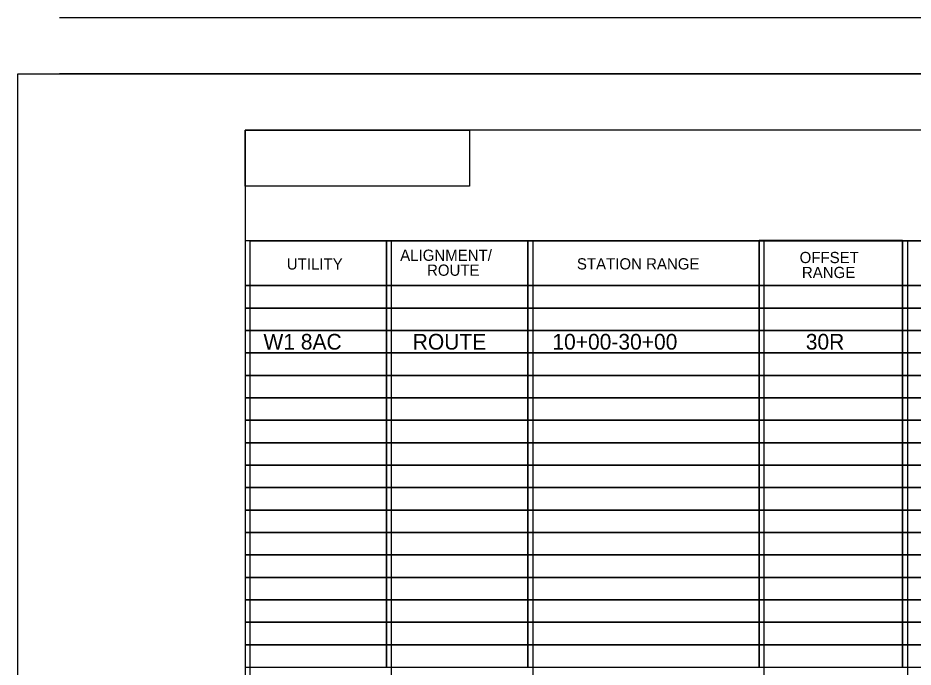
# Model space of a CAD drawing. Extents: x 11473 to 13269, y 16929 to 18079.
# Drawn here: x 11472.6 to 11871.5, y 17790 to 18079.4 of the extents above; entities that cross this region are included whole.
import ezdxf

# ---------------------------------------------------------------- set-up
doc = ezdxf.new("R2010")
doc.units = 0
for name, color, linetype in [('RD_SHT_Bndy', 7, 'Continuous'), ('RD_SHT_Iplotshp', 7, 'Continuous'), ('RD_SHT_Misc2', 7, 'Continuous'), ('RD_SHT_Snap', 7, 'Continuous'), ('RD_SHT_TX', 7, 'Continuous')]:
    doc.layers.add(name, color=color, linetype=linetype)

msp = doc.modelspace()

# ---------------------------------------------------------------- linework, layer by layer
at = {"layer": 'RD_SHT_Bndy'}
for p, q in [((13251.23, 18079.35), (11491.23, 18079.35)), ((13251.23, 18054.35), (11491.23, 18054.35)), ((13248.83, 18029.35), (11573.83, 18029.35)), ((11573.83, 18029.35), (11573.83, 16979.35))]:
    msp.add_line(p, q, dxfattribs=at)
for points in [[(11573.88, 18004.35), (11573.88, 18029.35), (11673.88, 18029.35), (11673.88, 18004.35)], [(11636.83, 17980), (11573.83, 17980), (11573.83, 17960), (11636.83, 17960)], [(11636.83, 17960), (11699.83, 17960), (11699.83, 17980), (11636.83, 17980)], [(11699.83, 17960), (11802.84, 17960), (11802.84, 17980), (11699.83, 17980)], [(11802.84, 17960), (11866.84, 17960), (11866.84, 17980.06), (11802.84, 17980.06)], [(11866.84, 17960), (11973.81, 17960), (11973.81, 17980.01), (11866.84, 17980.01)], [(11573.83, 17950), (11636.83, 17950), (11636.83, 17960), (11573.83, 17960)], [(11636.83, 17950), (11699.83, 17950), (11699.83, 17960), (11636.83, 17960)], [(11699.83, 17950), (11802.84, 17950), (11802.84, 17960), (11699.83, 17960)], [(11802.84, 17950), (11866.84, 17950), (11866.84, 17960), (11802.84, 17960)], [(11866.84, 17950), (11973.81, 17950), (11973.81, 17960), (11866.84, 17960)], [(11573.83, 17939.99), (11636.83, 17939.99), (11636.83, 17950), (11573.83, 17950)], [(11636.83, 17939.99), (11699.83, 17939.99), (11699.83, 17950), (11636.83, 17950)], [(11699.83, 17939.99), (11802.84, 17939.99), (11802.84, 17950), (11699.83, 17950)], [(11802.84, 17939.99), (11866.84, 17939.99), (11866.84, 17950), (11802.84, 17950)], [(11866.84, 17939.99), (11973.81, 17939.99), (11973.81, 17950), (11866.84, 17950)], [(11573.83, 17929.99), (11636.83, 17929.99), (11636.83, 17939.99), (11573.83, 17939.99)], [(11636.83, 17929.99), (11699.83, 17929.99), (11699.83, 17939.99), (11636.83, 17939.99)], [(11699.83, 17929.99), (11802.84, 17929.99), (11802.84, 17939.99), (11699.83, 17939.99)], [(11802.84, 17929.99), (11866.84, 17929.99), (11866.84, 17939.99), (11802.84, 17939.99)], [(11866.84, 17929.99), (11973.81, 17929.99), (11973.81, 17939.99), (11866.84, 17939.99)], [(11573.83, 17919.99), (11636.83, 17919.99), (11636.83, 17929.99), (11573.83, 17929.99)], [(11636.83, 17919.99), (11699.83, 17919.99), (11699.83, 17929.99), (11636.83, 17929.99)], [(11699.83, 17919.99), (11802.84, 17919.99), (11802.84, 17929.99), (11699.83, 17929.99)], [(11802.84, 17919.99), (11866.84, 17919.99), (11866.84, 17929.99), (11802.84, 17929.99)], [(11866.84, 17919.99), (11973.81, 17919.99), (11973.81, 17929.99), (11866.84, 17929.99)], [(11573.83, 17909.98), (11636.83, 17909.98), (11636.83, 17919.99), (11573.83, 17919.99)], [(11636.83, 17909.98), (11699.83, 17909.98), (11699.83, 17919.99), (11636.83, 17919.99)], [(11699.83, 17909.98), (11802.84, 17909.98), (11802.84, 17919.99), (11699.83, 17919.99)], [(11802.84, 17909.98), (11866.84, 17909.98), (11866.84, 17919.99), (11802.84, 17919.99)], [(11866.84, 17909.98), (11973.81, 17909.98), (11973.81, 17919.99), (11866.84, 17919.99)], [(11573.83, 17899.98), (11636.83, 17899.98), (11636.83, 17909.98), (11573.83, 17909.98)], [(11636.83, 17899.98), (11699.83, 17899.98), (11699.83, 17909.98), (11636.83, 17909.98)], [(11699.83, 17899.98), (11802.84, 17899.98), (11802.84, 17909.98), (11699.83, 17909.98)], [(11802.84, 17899.98), (11866.84, 17899.98), (11866.84, 17909.98), (11802.84, 17909.98)], [(11866.84, 17899.98), (11973.81, 17899.98), (11973.81, 17909.98), (11866.84, 17909.98)], [(11573.83, 17889.97), (11636.83, 17889.97), (11636.83, 17899.98), (11573.83, 17899.98)], [(11636.83, 17889.97), (11699.83, 17889.97), (11699.83, 17899.98), (11636.83, 17899.98)], [(11699.83, 17889.97), (11802.84, 17889.97), (11802.84, 17899.98), (11699.83, 17899.98)], [(11802.84, 17889.97), (11866.84, 17889.97), (11866.84, 17899.98), (11802.84, 17899.98)], [(11866.84, 17889.97), (11973.81, 17889.97), (11973.81, 17899.98), (11866.84, 17899.98)], [(11573.83, 17879.97), (11636.83, 17879.97), (11636.83, 17889.97), (11573.83, 17889.97)], [(11636.83, 17879.97), (11699.83, 17879.97), (11699.83, 17889.97), (11636.83, 17889.97)], [(11699.83, 17879.97), (11802.84, 17879.97), (11802.84, 17889.97), (11699.83, 17889.97)], [(11802.84, 17879.97), (11866.84, 17879.97), (11866.84, 17889.97), (11802.84, 17889.97)], [(11866.84, 17879.97), (11973.81, 17879.97), (11973.81, 17889.97), (11866.84, 17889.97)], [(11573.83, 17869.96), (11636.83, 17869.96), (11636.83, 17879.97), (11573.83, 17879.97)], [(11636.83, 17869.96), (11699.83, 17869.96), (11699.83, 17879.97), (11636.83, 17879.97)], [(11699.83, 17869.96), (11802.84, 17869.96), (11802.84, 17879.97), (11699.83, 17879.97)], [(11802.84, 17869.96), (11866.84, 17869.96), (11866.84, 17879.97), (11802.84, 17879.97)], [(11866.84, 17869.96), (11973.81, 17869.96), (11973.81, 17879.97), (11866.84, 17879.97)], [(11573.83, 17859.96), (11636.83, 17859.96), (11636.83, 17869.96), (11573.83, 17869.96)], [(11636.83, 17859.96), (11699.83, 17859.96), (11699.83, 17869.96), (11636.83, 17869.96)], [(11699.83, 17859.96), (11802.84, 17859.96), (11802.84, 17869.96), (11699.83, 17869.96)], [(11802.84, 17859.96), (11866.84, 17859.96), (11866.84, 17869.96), (11802.84, 17869.96)], [(11866.84, 17859.96), (11973.81, 17859.96), (11973.81, 17869.96), (11866.84, 17869.96)], [(11573.83, 17849.96), (11636.83, 17849.96), (11636.83, 17859.96), (11573.83, 17859.96)], [(11636.83, 17849.96), (11699.83, 17849.96), (11699.83, 17859.96), (11636.83, 17859.96)], [(11699.83, 17849.96), (11802.84, 17849.96), (11802.84, 17859.96), (11699.83, 17859.96)], [(11802.84, 17849.96), (11866.84, 17849.96), (11866.84, 17859.96), (11802.84, 17859.96)], [(11866.84, 17849.96), (11973.81, 17849.96), (11973.81, 17859.96), (11866.84, 17859.96)], [(11573.83, 17839.95), (11636.83, 17839.95), (11636.83, 17849.96), (11573.83, 17849.96)], [(11636.83, 17839.95), (11699.83, 17839.95), (11699.83, 17849.96), (11636.83, 17849.96)], [(11699.83, 17839.95), (11802.84, 17839.95), (11802.84, 17849.96), (11699.83, 17849.96)], [(11802.84, 17839.95), (11866.84, 17839.95), (11866.84, 17849.96), (11802.84, 17849.96)], [(11866.84, 17839.95), (11973.81, 17839.95), (11973.81, 17849.96), (11866.84, 17849.96)], [(11573.83, 17829.95), (11636.83, 17829.95), (11636.83, 17839.95), (11573.83, 17839.95)], [(11636.83, 17829.95), (11699.83, 17829.95), (11699.83, 17839.95), (11636.83, 17839.95)], [(11699.83, 17829.95), (11802.84, 17829.95), (11802.84, 17839.95), (11699.83, 17839.95)], [(11802.84, 17829.95), (11866.84, 17829.95), (11866.84, 17839.95), (11802.84, 17839.95)], [(11866.84, 17829.95), (11973.81, 17829.95), (11973.81, 17839.95), (11866.84, 17839.95)], [(11573.83, 17819.94), (11636.83, 17819.94), (11636.83, 17829.95), (11573.83, 17829.95)], [(11636.83, 17819.94), (11699.83, 17819.94), (11699.83, 17829.95), (11636.83, 17829.95)], [(11699.83, 17819.94), (11802.84, 17819.94), (11802.84, 17829.95), (11699.83, 17829.95)], [(11802.84, 17819.94), (11866.84, 17819.94), (11866.84, 17829.95), (11802.84, 17829.95)], [(11866.84, 17819.94), (11973.81, 17819.94), (11973.81, 17829.95), (11866.84, 17829.95)], [(11573.83, 17809.94), (11636.83, 17809.94), (11636.83, 17819.94), (11573.83, 17819.94)], [(11636.83, 17809.94), (11699.83, 17809.94), (11699.83, 17819.94), (11636.83, 17819.94)], [(11699.83, 17809.94), (11802.84, 17809.94), (11802.84, 17819.94), (11699.83, 17819.94)], [(11802.84, 17809.94), (11866.84, 17809.94), (11866.84, 17819.94), (11802.84, 17819.94)], [(11866.84, 17809.94), (11973.81, 17809.94), (11973.81, 17819.94), (11866.84, 17819.94)], [(11573.83, 17799.93), (11636.83, 17799.93), (11636.83, 17809.94), (11573.83, 17809.94)], [(11636.83, 17799.93), (11699.83, 17799.93), (11699.83, 17809.94), (11636.83, 17809.94)], [(11699.83, 17799.93), (11802.84, 17799.93), (11802.84, 17809.94), (11699.83, 17809.94)], [(11802.84, 17799.93), (11866.84, 17799.93), (11866.84, 17809.94), (11802.84, 17809.94)], [(11866.84, 17799.93), (11973.81, 17799.93), (11973.81, 17809.94), (11866.84, 17809.94)], [(11573.83, 17789.93), (11636.83, 17789.93), (11636.83, 17799.93), (11573.83, 17799.93)], [(11636.83, 17789.93), (11699.83, 17789.93), (11699.83, 17799.93), (11636.83, 17799.93)], [(11699.83, 17789.93), (11802.84, 17789.93), (11802.84, 17799.93), (11699.83, 17799.93)], [(11802.84, 17789.93), (11866.84, 17789.93), (11866.84, 17799.93), (11802.84, 17799.93)], [(11866.84, 17789.93), (11973.81, 17789.93), (11973.81, 17799.93), (11866.84, 17799.93)]]:
    msp.add_lwpolyline(points, close=True, dxfattribs=at)
at = {"layer": 'RD_SHT_Iplotshp'}
msp.add_lwpolyline([(11472.63, 18054.35), (13268.63, 18054.35), (13268.63, 16954.35), (11472.63, 16954.35)], close=True, dxfattribs=at)
at = {"layer": 'RD_SHT_Misc2'}
for p, q in [((11576, 17979.97), (13244, 17979.97)), ((11576, 17979.97), (11576, 17110)), ((11639, 17980), (11639, 17110)), ((11702, 17980), (11702, 17110)), ((11805, 17980), (11805, 17110)), ((11869.01, 17980.06), (11869.01, 17110)), ((11576, 17960), (13244, 17960)), ((11576, 17950), (13244, 17950)), ((11576, 17940), (13244, 17940)), ((11576, 17930), (13244, 17930)), ((11576, 17920), (13244, 17920)), ((11576, 17910), (13244, 17910)), ((11576, 17900), (13244, 17900)), ((11576, 17890), (13244, 17890)), ((11576, 17880), (13244, 17880)), ((11576, 17870), (13244, 17870)), ((11576, 17860), (13244, 17860)), ((11576, 17850), (13244, 17850)), ((11576, 17840), (13244, 17840)), ((11576, 17830), (13244, 17830)), ((11576, 17820), (13244, 17820)), ((11576, 17810), (13244, 17810)), ((11576, 17800), (13244, 17800)), ((11576, 17790), (13244, 17790))]:
    msp.add_line(p, q, dxfattribs=at)
at = {"layer": 'RD_SHT_Snap'}
msp.add_line((11472.63, 16954.35), (11472.63, 18054.35), dxfattribs=at)

# ---------------------------------------------------------------- texts
at = {"layer": 'RD_SHT_TX'}
for s, height, p in [('ALIGNMENT/', 5, (11642.96, 17971.06)), ('OFFSET', 5, (11820.94, 17970.05)), ('UTILITY', 5, (11592.45, 17967.18)), ('ROUTE', 5, (11654.92, 17964.4)), ('STATION RANGE', 5, (11721.7, 17967.22)), ('RANGE', 5, (11821.96, 17963.38)), ('W1 8AC', 7, (11582.04, 17931.49)), ('ROUTE', 7, (11648.54, 17931.49)), ('10+00-30+00', 7, (11710.77, 17931.49)), ('30R', 7, (11823.68, 17931.49))]:
    msp.add_text(s, height=height, dxfattribs=at).set_placement(p)

doc.saveas('drawing.dxf')
